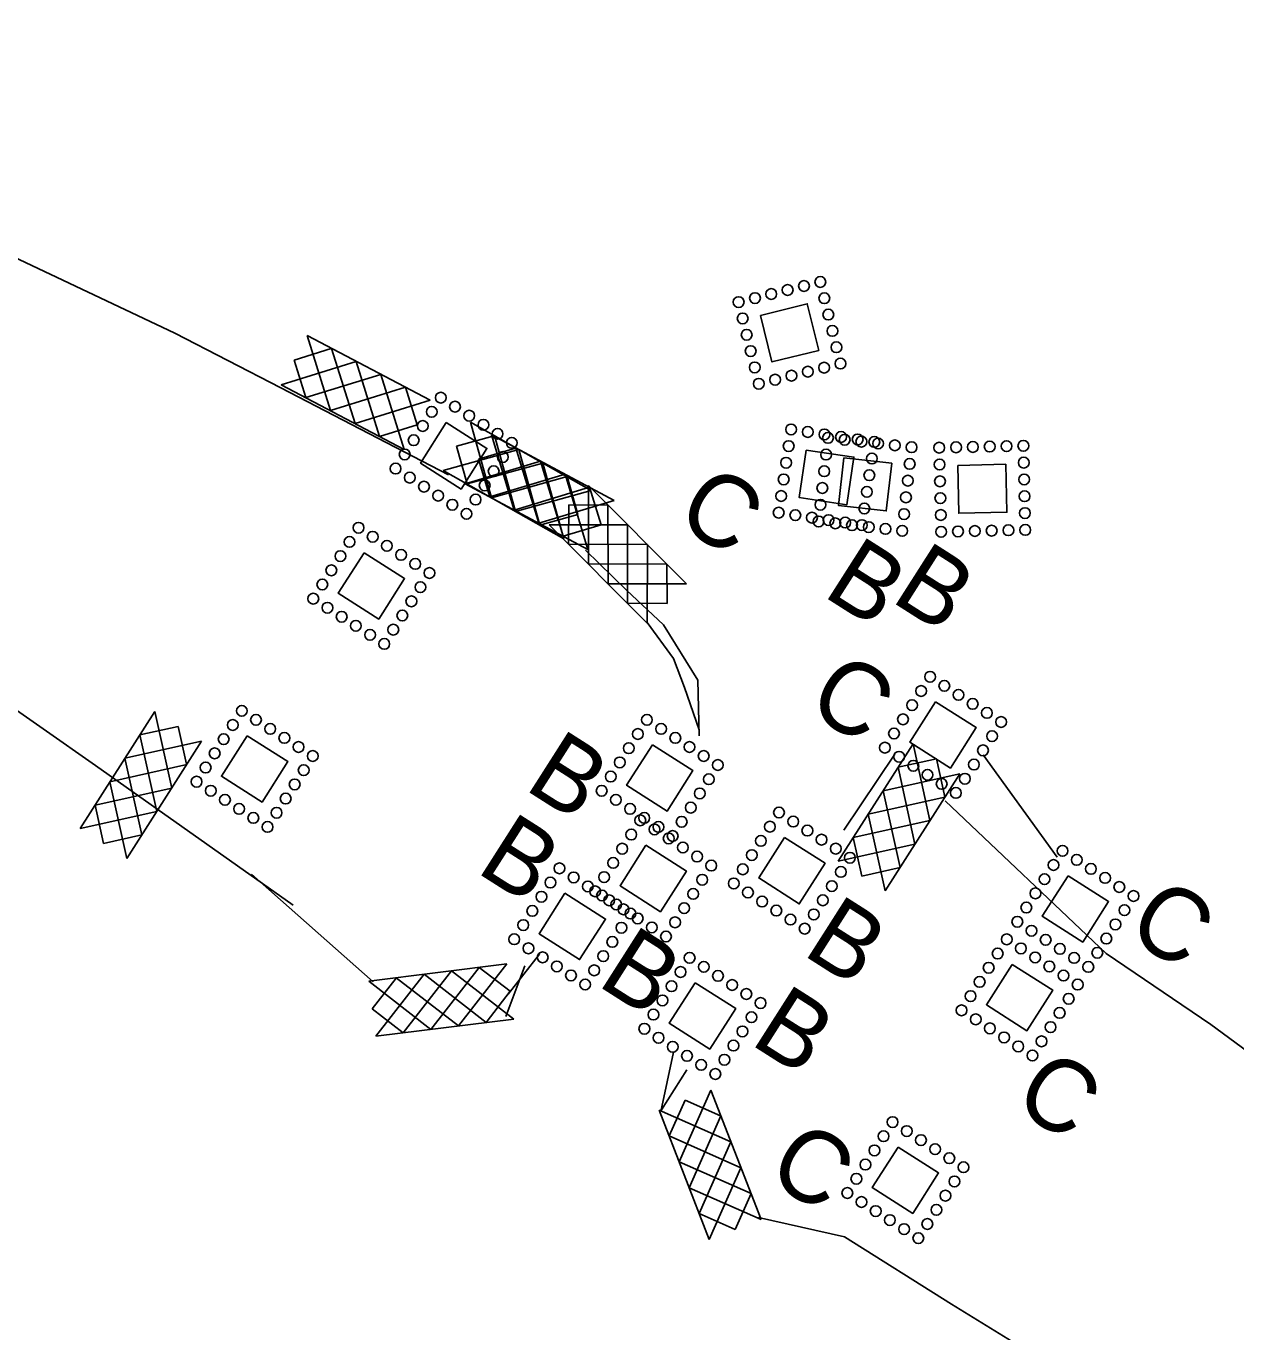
# Model space of a CAD drawing. Extents: x 2023536 to 2025544, y 819438 to 821266.
# Drawn here: x 2024579.5 to 2024831.1, y 820383.6 to 820655.3 of the extents above; entities that cross this region are included whole.
import ezdxf

# ---------------------------------------------------------------- set-up
doc = ezdxf.new("R2010")
doc.units = 0
for name, color, linetype in [('Label B Both CELL', 7, 'Continuous'), ('Label B CG CELL', 7, 'Continuous'), ('Label C Both CELL', 7, 'Continuous'), ('Label C Final CELL', 7, 'Continuous'), ('Rock Inlet Sediment Trap Type B Both CELL', 7, 'Continuous'), ('Rock Inlet Sediment Trap Type B CG CELL', 7, 'Continuous'), ('Rock Inlet Sediment Trap Type C Both CELL', 7, 'Continuous'), ('Rock Inlet Sediment Trap Type C Final CELL', 7, 'Continuous'), ('Rock Silt Check Type A Both CELL', 7, 'Continuous'), ('Rock Silt Check Type A CG CELL', 7, 'Continuous'), ('Rock Silt Check Type A Final CELL', 7, 'Continuous'), ('Temporary Silt Fence Both', 7, 'Continuous'), ('Temporary Silt Fence CG', 7, 'Continuous'), ('Temporary Silt Fence Final', 7, 'Continuous')]:
    doc.layers.add(name, color=color, linetype=linetype)

msp = doc.modelspace()

# ---------------------------------------------------------------- linework, layer by layer
at = {"layer": 'Rock Inlet Sediment Trap Type B Both CELL'}
for points in [[(2024749.55, 820565.48), (2024759.49, 820564.36), (2024758.37, 820554.43), (2024748.44, 820555.55)], [(2024773.22, 820563.91), (2024783.22, 820564.14), (2024783.45, 820554.14), (2024773.45, 820553.93)]]:
    msp.add_lwpolyline(points, close=True, dxfattribs=at)
for centre in [(2024746.24, 820569.63), (2024749.72, 820569.24), (2024753.19, 820568.85), (2024745.85, 820566.15), (2024756.67, 820568.46), (2024760.15, 820568.07), (2024763.63, 820567.68), (2024769.38, 820567.59), (2024772.88, 820567.67), (2024776.38, 820567.74), (2024779.88, 820567.82), (2024783.38, 820567.9), (2024786.88, 820567.98), (2024763.24, 820564.21), (2024769.46, 820564.09), (2024786.96, 820564.48), (2024745.46, 820562.68), (2024762.85, 820560.73), (2024787.04, 820560.98), (2024745.07, 820559.2), (2024769.54, 820560.59), (2024744.68, 820555.72), (2024762.46, 820557.25), (2024769.62, 820557.09), (2024787.12, 820557.48), (2024762.07, 820553.77), (2024769.7, 820553.59), (2024787.2, 820553.98), (2024744.29, 820552.24), (2024747.77, 820551.85), (2024751.24, 820551.46), (2024754.72, 820551.07), (2024758.2, 820550.68), (2024761.68, 820550.29), (2024769.78, 820550.09), (2024773.28, 820550.17), (2024776.78, 820550.25), (2024780.28, 820550.33), (2024783.77, 820550.41), (2024787.27, 820550.48)]:
    msp.add_circle(centre, 1.12, dxfattribs=at)
at = {"layer": 'Rock Inlet Sediment Trap Type B CG CELL'}
for points in [[(2024709.73, 820505.77), (2024718.16, 820500.4), (2024712.79, 820491.96), (2024704.36, 820497.35)], [(2024737.2, 820486.49), (2024745.63, 820481.12), (2024740.26, 820472.68), (2024731.83, 820478.07)], [(2024708.36, 820484.86), (2024716.79, 820479.48), (2024711.41, 820471.05), (2024702.99, 820476.44)], [(2024691.54, 820474.88), (2024699.98, 820469.5), (2024694.6, 820461.07), (2024686.17, 820466.45)], [(2024718.61, 820456.26), (2024727.05, 820450.88), (2024721.67, 820442.45), (2024713.24, 820447.84)]]:
    msp.add_lwpolyline(points, close=True, dxfattribs=at)
for centre in [(2024708.59, 820510.96), (2024711.54, 820509.08), (2024706.71, 820508.01), (2024714.49, 820507.2), (2024704.82, 820505.06), (2024717.44, 820505.32), (2024702.94, 820502.11), (2024720.39, 820503.44), (2024723.34, 820501.56), (2024701.06, 820499.16), (2024721.46, 820498.6), (2024699.18, 820496.2), (2024719.58, 820495.65), (2024702.13, 820494.32), (2024717.7, 820492.7), (2024705.08, 820492.44), (2024707.21, 820490.05), (2024708.03, 820490.56), (2024736.05, 820491.68), (2024710.16, 820488.17), (2024710.99, 820488.68), (2024715.82, 820489.75), (2024734.17, 820488.73), (2024739.01, 820489.8), (2024741.96, 820487.92), (2024705.33, 820487.1), (2024713.12, 820486.29), (2024713.94, 820486.8), (2024732.29, 820485.78), (2024744.91, 820486.04), (2024703.45, 820484.15), (2024716.07, 820484.4), (2024719.02, 820482.52), (2024730.41, 820482.83), (2024747.86, 820484.16), (2024750.81, 820482.27), (2024690.4, 820480.07), (2024701.57, 820481.19), (2024721.97, 820480.64), (2024728.53, 820479.87), (2024748.93, 820479.32), (2024688.52, 820477.11), (2024693.35, 820478.18), (2024699.69, 820478.24), (2024720.09, 820477.69), (2024726.65, 820476.92), (2024686.64, 820474.16), (2024696.3, 820476.3), (2024697.81, 820475.29), (2024699.25, 820474.42), (2024718.21, 820474.74), (2024729.6, 820475.04), (2024747.05, 820476.37), (2024684.76, 820471.21), (2024700.76, 820473.41), (2024702.21, 820472.54), (2024703.71, 820471.53), (2024716.33, 820471.79), (2024732.55, 820473.16), (2024735.5, 820471.28), (2024745.17, 820473.42), (2024682.87, 820468.26), (2024705.16, 820470.66), (2024706.66, 820469.65), (2024714.44, 820468.84), (2024738.45, 820469.4), (2024743.29, 820470.47), (2024703.28, 820467.71), (2024709.61, 820467.77), (2024712.56, 820465.88), (2024741.4, 820467.52), (2024680.99, 820465.31), (2024683.94, 820463.43), (2024701.39, 820464.76), (2024686.9, 820461.55), (2024699.51, 820461.8), (2024717.47, 820461.45), (2024689.85, 820459.66), (2024692.8, 820457.78), (2024697.63, 820458.85), (2024715.59, 820458.5), (2024720.42, 820459.57), (2024723.37, 820457.69), (2024695.75, 820455.9), (2024713.71, 820455.54), (2024726.32, 820455.8), (2024711.82, 820452.59), (2024729.27, 820453.92), (2024732.23, 820452.04), (2024709.94, 820449.64), (2024708.06, 820446.69), (2024730.34, 820449.09), (2024711.01, 820444.81), (2024728.46, 820446.14), (2024713.96, 820442.93), (2024726.58, 820443.19), (2024716.92, 820441.05), (2024719.87, 820439.17), (2024724.7, 820440.24), (2024722.82, 820437.28)]:
    msp.add_circle(centre, 1.12, dxfattribs=at)
at = {"layer": 'Rock Inlet Sediment Trap Type C Both CELL'}
for points in [[(2024741.74, 820567.09), (2024751.63, 820565.62), (2024750.15, 820555.73), (2024740.26, 820557.22)], [(2024768.63, 820514.73), (2024777.07, 820509.35), (2024771.69, 820500.92), (2024763.27, 820506.3)]]:
    msp.add_lwpolyline(points, close=True, dxfattribs=at)
for centre in [(2024738.58, 820571.38), (2024742.04, 820570.86), (2024745.5, 820570.34), (2024748.96, 820569.82), (2024752.42, 820569.31), (2024755.89, 820568.79), (2024738.06, 820567.92), (2024737.54, 820564.46), (2024755.37, 820565.33), (2024737.02, 820560.99), (2024754.85, 820561.86), (2024754.33, 820558.4), (2024736.51, 820557.53), (2024735.99, 820554.07), (2024739.45, 820553.55), (2024742.91, 820553.03), (2024746.37, 820552.52), (2024753.81, 820554.94), (2024749.83, 820552), (2024753.29, 820551.48), (2024767.49, 820519.92), (2024770.44, 820518.04), (2024765.61, 820516.97), (2024773.39, 820516.16), (2024763.73, 820514.02), (2024776.34, 820514.28), (2024779.3, 820512.4), (2024761.85, 820511.07), (2024782.25, 820510.52), (2024759.97, 820508.12), (2024780.37, 820507.57), (2024758.08, 820505.17), (2024778.49, 820504.61), (2024761.04, 820503.29), (2024763.99, 820501.4), (2024776.6, 820501.66), (2024766.94, 820499.52), (2024774.72, 820498.71), (2024769.89, 820497.64), (2024772.84, 820495.76)]:
    msp.add_circle(centre, 1.12, dxfattribs=at)
at = {"layer": 'Rock Inlet Sediment Trap Type C Final CELL'}
for points in [[(2024732.21, 820595.12), (2024741.92, 820597.52), (2024744.31, 820587.81), (2024734.6, 820585.43)], [(2024666.87, 820572.8), (2024675.3, 820567.43), (2024669.93, 820558.99), (2024661.5, 820564.38)], [(2024649.75, 820545.73), (2024658.18, 820540.36), (2024652.81, 820531.92), (2024644.38, 820537.31)], [(2024625.48, 820507.65), (2024633.91, 820502.27), (2024628.54, 820493.84), (2024620.11, 820499.22)], [(2024796.17, 820478.52), (2024804.6, 820473.14), (2024799.23, 820464.71), (2024790.8, 820470.09)], [(2024784.57, 820460.09), (2024793, 820454.72), (2024787.62, 820446.29), (2024779.2, 820451.67)], [(2024760.82, 820422.08), (2024769.25, 820416.71), (2024763.88, 820408.28), (2024755.45, 820413.66)]]:
    msp.add_lwpolyline(points, close=True, dxfattribs=at)
for centre in [(2024744.65, 820602.07), (2024731.06, 820598.72), (2024734.45, 820599.56), (2024737.85, 820600.4), (2024741.25, 820601.23), (2024745.49, 820598.68), (2024727.66, 820597.88), (2024728.5, 820594.48), (2024746.32, 820595.28), (2024729.33, 820591.08), (2024747.16, 820591.88), (2024748, 820588.48), (2024730.17, 820587.69), (2024748.84, 820585.08), (2024731.01, 820584.29), (2024738.65, 820582.57), (2024742.05, 820583.41), (2024745.44, 820584.24), (2024731.85, 820580.89), (2024735.25, 820581.73), (2024665.72, 820578), (2024663.84, 820575.05), (2024668.68, 820576.12), (2024671.63, 820574.24), (2024661.96, 820572.1), (2024674.58, 820572.35), (2024660.08, 820569.14), (2024677.53, 820570.47), (2024658.2, 820566.19), (2024680.48, 820568.59), (2024678.6, 820565.64), (2024656.32, 820563.24), (2024659.27, 820561.36), (2024676.72, 820562.69), (2024662.22, 820559.48), (2024674.84, 820559.74), (2024665.17, 820557.6), (2024668.12, 820555.72), (2024672.96, 820556.79), (2024671.07, 820553.83), (2024648.61, 820550.93), (2024646.73, 820547.98), (2024651.56, 820549.05), (2024654.51, 820547.17), (2024644.84, 820545.03), (2024657.46, 820545.28), (2024642.96, 820542.07), (2024660.41, 820543.4), (2024641.08, 820539.12), (2024663.36, 820541.52), (2024639.2, 820536.17), (2024661.48, 820538.57), (2024642.15, 820534.29), (2024659.6, 820535.62), (2024645.1, 820532.41), (2024657.72, 820532.67), (2024648.05, 820530.53), (2024651.01, 820528.65), (2024655.84, 820529.72), (2024653.96, 820526.76), (2024624.34, 820512.84), (2024622.45, 820509.89), (2024627.29, 820510.96), (2024630.24, 820509.08), (2024620.57, 820506.94), (2024633.19, 820507.2), (2024618.69, 820503.99), (2024636.14, 820505.32), (2024616.81, 820501.04), (2024639.09, 820503.44), (2024637.21, 820500.49), (2024614.93, 820498.09), (2024617.88, 820496.21), (2024635.33, 820497.53), (2024620.83, 820494.32), (2024633.45, 820494.58), (2024623.78, 820492.44), (2024626.73, 820490.56), (2024631.57, 820491.63), (2024629.69, 820488.68), (2024795.03, 820483.71), (2024797.98, 820481.83), (2024793.15, 820480.76), (2024800.93, 820479.95), (2024791.27, 820477.81), (2024803.88, 820478.07), (2024789.38, 820474.86), (2024806.83, 820476.19), (2024809.79, 820474.31), (2024787.5, 820471.91), (2024807.9, 820471.36), (2024785.62, 820468.96), (2024806.02, 820468.4), (2024788.57, 820467.08), (2024783.42, 820465.29), (2024786.37, 820463.41), (2024791.52, 820465.19), (2024794.48, 820463.31), (2024804.14, 820465.45), (2024781.54, 820462.34), (2024789.33, 820461.53), (2024797.43, 820461.43), (2024802.26, 820462.5), (2024779.66, 820459.39), (2024792.28, 820459.65), (2024795.23, 820457.76), (2024800.38, 820459.55), (2024777.78, 820456.44), (2024798.18, 820455.88), (2024775.9, 820453.48), (2024796.3, 820452.93), (2024774.02, 820450.53), (2024794.42, 820449.98), (2024776.97, 820448.65), (2024779.92, 820446.77), (2024792.54, 820447.03), (2024782.87, 820444.89), (2024790.66, 820444.08), (2024785.82, 820443.01), (2024788.77, 820441.13), (2024759.68, 820427.28), (2024762.63, 820425.4), (2024757.8, 820424.33), (2024765.58, 820423.52), (2024755.91, 820421.38), (2024768.53, 820421.64), (2024771.48, 820419.76), (2024754.03, 820418.43), (2024774.43, 820417.87), (2024752.15, 820415.48), (2024772.55, 820414.92), (2024750.27, 820412.52), (2024770.67, 820411.97), (2024753.22, 820410.64), (2024756.17, 820408.76), (2024768.79, 820409.02), (2024759.12, 820406.88), (2024766.91, 820406.07), (2024762.08, 820405), (2024765.03, 820403.12)]:
    msp.add_circle(centre, 1.12, dxfattribs=at)
at = {"layer": 'Rock Silt Check Type A Both CELL'}
for p, q in [((2024650.77, 820456.58), (2024679.44, 820460.18)), ((2024667.98, 820458.74), (2024657.91, 820445.84)), ((2024673.69, 820459.47), (2024663.67, 820446.56)), ((2024680.88, 820448.72), (2024667.98, 820458.74)), ((2024679.44, 820460.18), (2024669.42, 820447.28)), ((2024680.17, 820454.48), (2024673.69, 820459.47)), ((2024663.67, 820446.56), (2024650.77, 820456.58)), ((2024656.43, 820457.24), (2024651.47, 820450.87)), ((2024662.23, 820458.02), (2024652.21, 820445.12)), ((2024669.42, 820447.28), (2024656.47, 820457.3)), ((2024675.13, 820448), (2024662.23, 820458.02)), ((2024680.17, 820454.48), (2024675.13, 820448)), ((2024657.91, 820445.84), (2024651.47, 820450.87)), ((2024652.21, 820445.12), (2024680.88, 820448.72)), ((2024713.19, 820424.4), (2024716.52, 820431.86)), ((2024715.29, 820418.99), (2024721.88, 820433.93)), ((2024723.9, 820428.6), (2024716.52, 820431.86)), ((2024721.88, 820433.93), (2024732.33, 820406.98)), ((2024726.06, 820423.16), (2024711.11, 820429.76)), ((2024711.11, 820429.76), (2024721.56, 820402.81)), ((2024717.38, 820413.58), (2024723.96, 820428.57)), ((2024728.15, 820417.75), (2024713.19, 820424.4)), ((2024719.46, 820408.22), (2024726.06, 820423.16)), ((2024730.24, 820412.4), (2024715.29, 820418.99)), ((2024721.56, 820402.81), (2024728.15, 820417.75)), ((2024732.33, 820406.98), (2024717.38, 820413.58)), ((2024726.97, 820404.89), (2024730.24, 820412.4)), ((2024726.97, 820404.89), (2024719.46, 820408.22))]:
    msp.add_line(p, q, dxfattribs=at)
at = {"layer": 'Rock Silt Check Type A CG CELL'}
for p, q in [((2024671.87, 820572.92), (2024697.02, 820558.69)), ((2024676.23, 820557.18), (2024671.87, 820572.92)), ((2024676.8, 820570.07), (2024669.02, 820567.92)), ((2024681.28, 820554.33), (2024676.87, 820570.09)), ((2024681.92, 820567.24), (2024666.18, 820562.87)), ((2024671.18, 820560.04), (2024669.02, 820567.92)), ((2024686.29, 820551.5), (2024681.92, 820567.24)), ((2024666.18, 820562.87), (2024691.34, 820548.64)), ((2024686.97, 820564.38), (2024671.18, 820560.04)), ((2024691.34, 820548.64), (2024686.97, 820564.38)), ((2024691.98, 820561.56), (2024676.23, 820557.18)), ((2024694.2, 820553.68), (2024691.98, 820561.56)), ((2024696.41, 820543.39), (2024696.42, 820559.72)), ((2024696.42, 820559.72), (2024716.84, 820539.27)), ((2024697.02, 820558.69), (2024681.28, 820554.33)), ((2024694.2, 820553.68), (2024686.29, 820551.5)), ((2024692.31, 820547.49), (2024692.34, 820555.67)), ((2024700.41, 820555.65), (2024692.34, 820555.67)), ((2024700.51, 820539.28), (2024700.49, 820555.65)), ((2024704.58, 820551.55), (2024688.25, 820551.56)), ((2024688.25, 820551.56), (2024708.67, 820531.11)), ((2024704.57, 820535.21), (2024704.58, 820551.55)), ((2024708.68, 820547.44), (2024692.31, 820547.49)), ((2024708.67, 820531.11), (2024708.68, 820547.44)), ((2024712.75, 820543.38), (2024696.41, 820543.39)), ((2024712.78, 820535.2), (2024712.75, 820543.38)), ((2024716.84, 820539.27), (2024700.51, 820539.28)), ((2024712.78, 820535.2), (2024704.57, 820535.21)), ((2024763.93, 820505.94), (2024748.39, 820481.57)), ((2024767.46, 820489.99), (2024763.93, 820505.94)), ((2024760.84, 820501.09), (2024768.82, 820502.83)), ((2024770.56, 820494.95), (2024768.82, 820502.83)), ((2024757.72, 820496.2), (2024773.67, 820499.73)), ((2024773.67, 820499.73), (2024758.13, 820475.36)), ((2024764.34, 820485.1), (2024760.84, 820501.09)), ((2024754.6, 820491.31), (2024770.58, 820494.88)), ((2024761.26, 820480.25), (2024757.72, 820496.2)), ((2024758.13, 820475.36), (2024754.6, 820491.31)), ((2024751.51, 820486.46), (2024767.46, 820489.99)), ((2024753.28, 820478.44), (2024751.51, 820486.46)), ((2024748.39, 820481.57), (2024764.34, 820485.1)), ((2024753.28, 820478.44), (2024761.26, 820480.25))]:
    msp.add_line(p, q, dxfattribs=at)
at = {"layer": 'Rock Silt Check Type A Final CELL'}
for p, q in [((2024637.91, 820590.91), (2024663.48, 820577.46)), ((2024642.75, 820575.31), (2024637.91, 820590.91)), ((2024642.93, 820588.22), (2024635.22, 820585.83)), ((2024647.88, 820572.61), (2024642.99, 820588.24)), ((2024648.13, 820585.54), (2024632.53, 820580.69)), ((2024637.62, 820578.01), (2024635.22, 820585.83)), ((2024652.97, 820569.94), (2024648.13, 820585.54)), ((2024653.26, 820582.84), (2024637.62, 820578.01)), ((2024658.1, 820567.24), (2024653.26, 820582.84)), ((2024632.53, 820580.69), (2024658.1, 820567.24)), ((2024658.35, 820580.17), (2024642.75, 820575.31)), ((2024660.82, 820572.36), (2024658.35, 820580.17)), ((2024663.48, 820577.46), (2024647.88, 820572.61)), ((2024660.82, 820572.36), (2024652.97, 820569.94)), ((2024676.27, 820570.24), (2024701.75, 820556.61)), ((2024681.01, 820554.61), (2024676.27, 820570.24)), ((2024681.27, 820567.51), (2024673.55, 820565.18)), ((2024686.12, 820551.87), (2024681.34, 820567.53)), ((2024686.45, 820564.79), (2024670.82, 820560.06)), ((2024675.89, 820557.34), (2024673.55, 820565.18)), ((2024691.19, 820549.16), (2024686.45, 820564.79)), ((2024691.57, 820562.06), (2024675.89, 820557.34)), ((2024696.3, 820546.42), (2024691.57, 820562.06)), ((2024670.82, 820560.06), (2024696.3, 820546.42)), ((2024696.64, 820559.36), (2024681.01, 820554.61)), ((2024699.05, 820551.53), (2024696.64, 820559.36)), ((2024701.75, 820556.61), (2024686.12, 820551.87)), ((2024699.05, 820551.53), (2024691.19, 820549.16)), ((2024606.22, 820512.71), (2024590.69, 820488.34)), ((2024609.75, 820496.77), (2024606.22, 820512.71)), ((2024603.13, 820507.87), (2024611.12, 820509.61)), ((2024606.64, 820491.88), (2024603.13, 820507.87)), ((2024612.86, 820501.73), (2024611.12, 820509.61)), ((2024600.01, 820502.97), (2024615.96, 820506.51)), ((2024615.96, 820506.51), (2024600.43, 820482.14)), ((2024603.56, 820487.02), (2024600.01, 820502.97)), ((2024596.9, 820498.08), (2024612.87, 820501.66)), ((2024593.81, 820493.23), (2024609.75, 820496.77)), ((2024600.43, 820482.14), (2024596.9, 820498.08)), ((2024590.69, 820488.34), (2024606.64, 820491.88)), ((2024595.57, 820485.22), (2024593.81, 820493.23)), ((2024595.57, 820485.22), (2024603.56, 820487.02))]:
    msp.add_line(p, q, dxfattribs=at)
at = {"layer": 'Temporary Silt Fence Both'}
msp.add_line((2024626.34, 820478.82), (2024651.68, 820456.43), dxfattribs=at)
for points in [[(2024451.18, 820671.39), (2024467.65, 820668.95), (2024491.66, 820653.24), (2024516.25, 820637.16), (2024532.28, 820626.95), (2024574.19, 820608.57), (2024610.4, 820591.43), (2024632.45, 820580.05)], [(2024804.11, 820462.38), (2024825.87, 820447.55), (2024844.01, 820434.21), (2024867.37, 820417.27), (2024893.46, 820399.52), (2024922.15, 820379.6), (2024933.13, 820372.39), (2024970.79, 820336.3)], [(2024731.77, 820407.43), (2024749.69, 820403.39), (2024771.9, 820389.37), (2024789.09, 820378.83), (2024803.6, 820370.94)]]:
    msp.add_lwpolyline(points, dxfattribs=at)
at = {"layer": 'Temporary Silt Fence CG'}
for p, q in [((2024632.45, 820580.05), (2024667.29, 820561.94)), ((2024770.63, 820494.09), (2024804.11, 820462.38)), ((2024679.72, 820453.91), (2024686.28, 820462.2)), ((2024714.1, 820441.83), (2024711.5, 820429.46))]:
    msp.add_line(p, q, dxfattribs=at)
for points in [[(2024473.45, 820583.78), (2024493.97, 820567.43), (2024517.82, 820552.44), (2024561.2, 820524.37), (2024593.94, 820501.46), (2024635.05, 820472.39)], [(2024708.62, 820531.21), (2024714.13, 820523.7), (2024716.4, 820517.69), (2024719.46, 820508.91)]]:
    msp.add_lwpolyline(points, dxfattribs=at)
at = {"layer": 'Temporary Silt Fence Final'}
for p, q in [((2024760.14, 820503.79), (2024749.54, 820488)), ((2024778.52, 820503.69), (2024793.91, 820482.4)), ((2024679.28, 820449.24), (2024683.17, 820459.81)), ((2024711.61, 820429.84), (2024716.91, 820438.15))]:
    msp.add_line(p, q, dxfattribs=at)
msp.add_lwpolyline([(2024695.84, 820546.24), (2024704.35, 820537.94), (2024712.04, 820530.72), (2024719.18, 820519.2), (2024719.48, 820507.67)], dxfattribs=at)

# ---------------------------------------------------------------- texts
at = {"layer": 'Label B Both CELL'}
for p in [(2024744.85, 820536.95), (2024758.99, 820535.85)]:
    msp.add_text('B', height=15, rotation=327.4893, dxfattribs=at).set_placement(p)
at = {"layer": 'Label B CG CELL'}
for p in [(2024682.79, 820496.71), (2024672.75, 820479.47), (2024740.64, 820462.3), (2024697.91, 820455.93), (2024729.74, 820443.7)]:
    msp.add_text('B', height=15, rotation=327.4893, dxfattribs=at).set_placement(p)
at = {"layer": 'Label C Both CELL'}
for p in [(2024714.03, 820552.19), (2024741.31, 820513.18)]:
    msp.add_text('C', height=15, rotation=327.4893, dxfattribs=at).set_placement(p)
at = {"layer": 'Label C Final CELL'}
for p in [(2024807.81, 820466.25), (2024784.25, 820430.58), (2024732.98, 820415.72)]:
    msp.add_text('C', height=15, rotation=327.4893, dxfattribs=at).set_placement(p)

doc.saveas('drawing.dxf')
